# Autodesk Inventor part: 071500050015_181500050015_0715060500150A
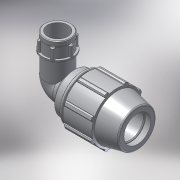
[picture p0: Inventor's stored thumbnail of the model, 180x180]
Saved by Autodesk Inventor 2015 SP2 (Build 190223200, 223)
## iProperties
Created: 2017-02
Part Number: 071500050015_181500050015_0715060500150A
Material: PVC-Piping
Description: PLASSON 90° ELBOW FEMALE ADAPTOR 50-1.1/2"
Document SubType Name: Modeling
Designer: KIM
Mass: 92.6774 g
Surface Area: 199.44 cm^2
Volume: 66.1981 cm^3
Density: 1.4 g/cm^3
Appearance: Smooth - White
Author: KIM
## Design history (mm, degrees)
derived "07150.ipt"
feature "Solid1::07150.ipt"
tag "TaggingFeature1"
body "Solid1"
other parameters: "d4" = 11.25, "d5" = 33.75, "d7" = 96, "d9" = 19.28571, "d11" = 4.5, "d13" = 120 deg, "d15" = 12 deg, "d16" = 83.52, "d18" = 2.5, "d19" = 35 deg, "d20" = 17.5 deg, "d21" = 89.28, "d23" = 0, "d25" = 360 deg, "d27" = 1.92, "d33" = 1, "d42" = 49.95, "d43" = 2.88, "d46" = 1.5, "d51" = 135, "d68" = 4.5, "d72" = 66, "d73" = 58.2985, "d74" = 25, "d75" = 67.04327, "d76" = 44.845, "d77" = 27.5, "d79" = 17.938, "d80" = 1.34535, "d83" = 0, "d84" = 0, "d91" = 72, "d93" = 93, "d94" = 44.845, "d95" = 31.3915, "d96" = 13.5, "d97" = 50 deg, "d98" = 40.3605, "d99" = 0.5, "d100" = 0.5, "d101" = 8.33333, "d102" = 58.2985, "d103" = 21.25, "d104" = 0, "d108" = 360 deg, "d110" = 1.74896, "E_" = 96, "A_" = 135, "l_" = 93, "l_2" = 25, "A_1" = 66, "Rp_" = 44.845, "d105" = 8.74478
